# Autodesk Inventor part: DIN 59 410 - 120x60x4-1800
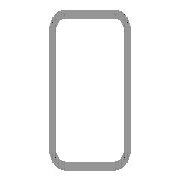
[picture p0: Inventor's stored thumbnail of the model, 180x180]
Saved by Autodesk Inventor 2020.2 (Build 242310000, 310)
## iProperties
Manager: www.cadconsulting.pl
Company: Fabian Stasiak CAD Consulting
_CCFamilyMember: 190
_CCFamilyDisplayName: DIN 59410 (Prostokąt) - Rurki stalowe o przekroju prostokątnym formowane na gorąco — Standard DIN 59410 (Prostokąt) został wycofany i zastąpiony przez standard 
_FrameMemberDoc: Frame Member File
_Version: 15.0.0
_GetPNFromCC: 1
IsCustomPart: 1
Created: 2015-02
Part Number: DIN 59 410 - 120x60x4-1800
Material: Stal, miękka
Description: Rurki stalowe o przekroju prostokątnym formowane na gorąco
Document SubType Name: Modellieren
Standard: DIN
Designer: F.Stasiak
Standards Organization: DIN
Language: pl-PL
Size Designation: 120x60x4
Categories: <MemberInstance><Categories><Category DisplayName="Kształtowniki konstrukcyjne" InternalName="089c4875-fa83-4c05-b084-43b9cc11f5ed" Mnemonic="GRDR"><CategoryPar
Stock Number: 120x60x4
Density: 7.85 g/cm^3
Appearance: Częściowo polerowany
Catalog Web Link: www.expertbooks.pl
G_L: 1800,000 mm
G_W: 60,000 mm
G_H: 120,000 mm
Author: F.Stasiak
Subject: Zbiór ćwiczeń. Autodesk Inventor 2020. Kurs Professional
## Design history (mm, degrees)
node "Płaszczyzna początkowa"
node "Płaszczyzna końcowa"
sketch "Szkic"
  geometry: L1 (-22, 60)-(22, 60); L2 (30, 52)-(30, -52); L3 (22, -60)-(-22, -60); L4 (-30, -52)-(-30, 52); L5 (-44.32, 0)-(44.32, 0) reference; L6 (0, -86.32)-(0, 86.32) reference; L7 (-22, 56)-(22, 56); L8 (26, 52)-(26, -52); L9 (22, -56)-(-22, -56); L10 (-26, -52)-(-26, 52); A1 r 8 centre (-22, 52) between (-22, 60) and (-30, 52); A2 r 8 centre (22, 52) between (30, 52) and (22, 60); A3 r 8 centre (22, -52) between (22, -60) and (30, -52); A4 r 8 centre (-22, -52) between (-30, -52) and (-22, -60); A5 r 4 centre (-22, 52) between (-22, 56) and (-26, 52); A6 r 4 centre (22, 52) between (26, 52) and (22, 56); A7 r 4 centre (22, -52) between (22, -56) and (26, -52); A8 r 4 centre (-22, -52) between (-26, -52) and (-22, -56); 3 further points
  constraints: 16 end point, 16 point on circle, 8 centre point, 8 tangent, 6 point on line, 4 parallel, 3 equal radius, 2 perpendicular, 1 horizontal, 7 other
  dimensions: "b" = 60 distance of point (-30, 60) point (30, 60); "ParH" = 120 distance of point (30, 60) point (30, -60); "msp_r" = 8 radius of A1 (= 2 x ParT); "d8" = 30 distance between parallel lines of L4 L6 (= 0.5 x b); "d9" = 60 distance between parallel lines of L5 L1 (= 0.5 x ParH); "d10" = 4 distance between parallel lines of L4 L10 (= ParT)
extrude "Bryła" new body sketch "Szkic" taper "d4" = 0 deg; stored distance "NLG" = 10
node "Driven Length"
  sketch "Sketch2"
    geometry: L1 (0, 0)-(10, 0) reference
    constraints: 2 end point, 1 horizontal
  workplane "Work Plane3"
  sketch "Sketch3"
    geometry: L1 (-2, 0)-(12, 0) reference; L2 (-2, 1800)-(12, 1800) reference
    dimensions: "d14" = 1800 distance between parallel lines of L1 L2 (derived)
body "Solid1"
other parameters: "ParT" = 4, "G_OFFSET_START" = 0 [user parameter; used in 1 equation term], "G_OFFSET_END" = 0 [user parameter; used in 1 equation term], "d11" = 0 (computed from G_OFFSET_START), "G_L" = 1800 (= d14) [user parameter], "d13" = 90 deg
